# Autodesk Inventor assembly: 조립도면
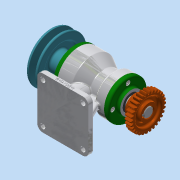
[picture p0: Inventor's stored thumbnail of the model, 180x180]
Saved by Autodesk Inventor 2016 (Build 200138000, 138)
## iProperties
Created: 2019-01
Part Number: 조립도면
Material: 일반
Document SubType Name: Assembly
Designer: 3sil_cad018
Author: 3sil_cad018
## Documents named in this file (15)
- C:\Users\3sil_cad018\Desktop\490107V1032\조립도면.iam
- C:\Users\3sil_cad018\Desktop\490107V1032\본체.ipt
- C:\Users\3sil_cad018\Desktop\490107V1032\앞커버.ipt
- C:\Users\3sil_cad018\Desktop\490107V1032\뒤커버.ipt
- C:\Users\3sil_cad018\Desktop\490107V1032\볼트 M4.ipt
- C:\Users\3sil_cad018\Desktop\490107V1032\오일 실 17 30 8.ipt
- C:\Users\3sil_cad018\Desktop\490107V1032\오일 실 25 38 8.ipt
- C:\Users\3sil_cad018\Desktop\490107V1032\V-벨트풀리.ipt
- C:\Users\3sil_cad018\Desktop\490107V1032\멈춤나사 M3.ipt
- C:\Users\3sil_cad018\Desktop\490107V1032\베어링 6203.ipt
- C:\Users\3sil_cad018\Desktop\490107V1032\베어링 6205.ipt
- C:\Users\3sil_cad018\Desktop\490107V1032\스퍼기어.ipt
- C:\Users\3sil_cad018\Desktop\490107V1032\축.ipt
- C:\Users\3sil_cad018\Desktop\490107V1032\키 5 x 5 x 20.ipt
- C:\Users\3sil_cad018\Desktop\490107V1032\키 6 x 6 x 18.ipt
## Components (1 placed, 1 different names)
1. V-벨트풀리:1 — 각도:4
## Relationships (1: Angle 1)
- 각도:4 [Angle]: V-벨트풀리:1
